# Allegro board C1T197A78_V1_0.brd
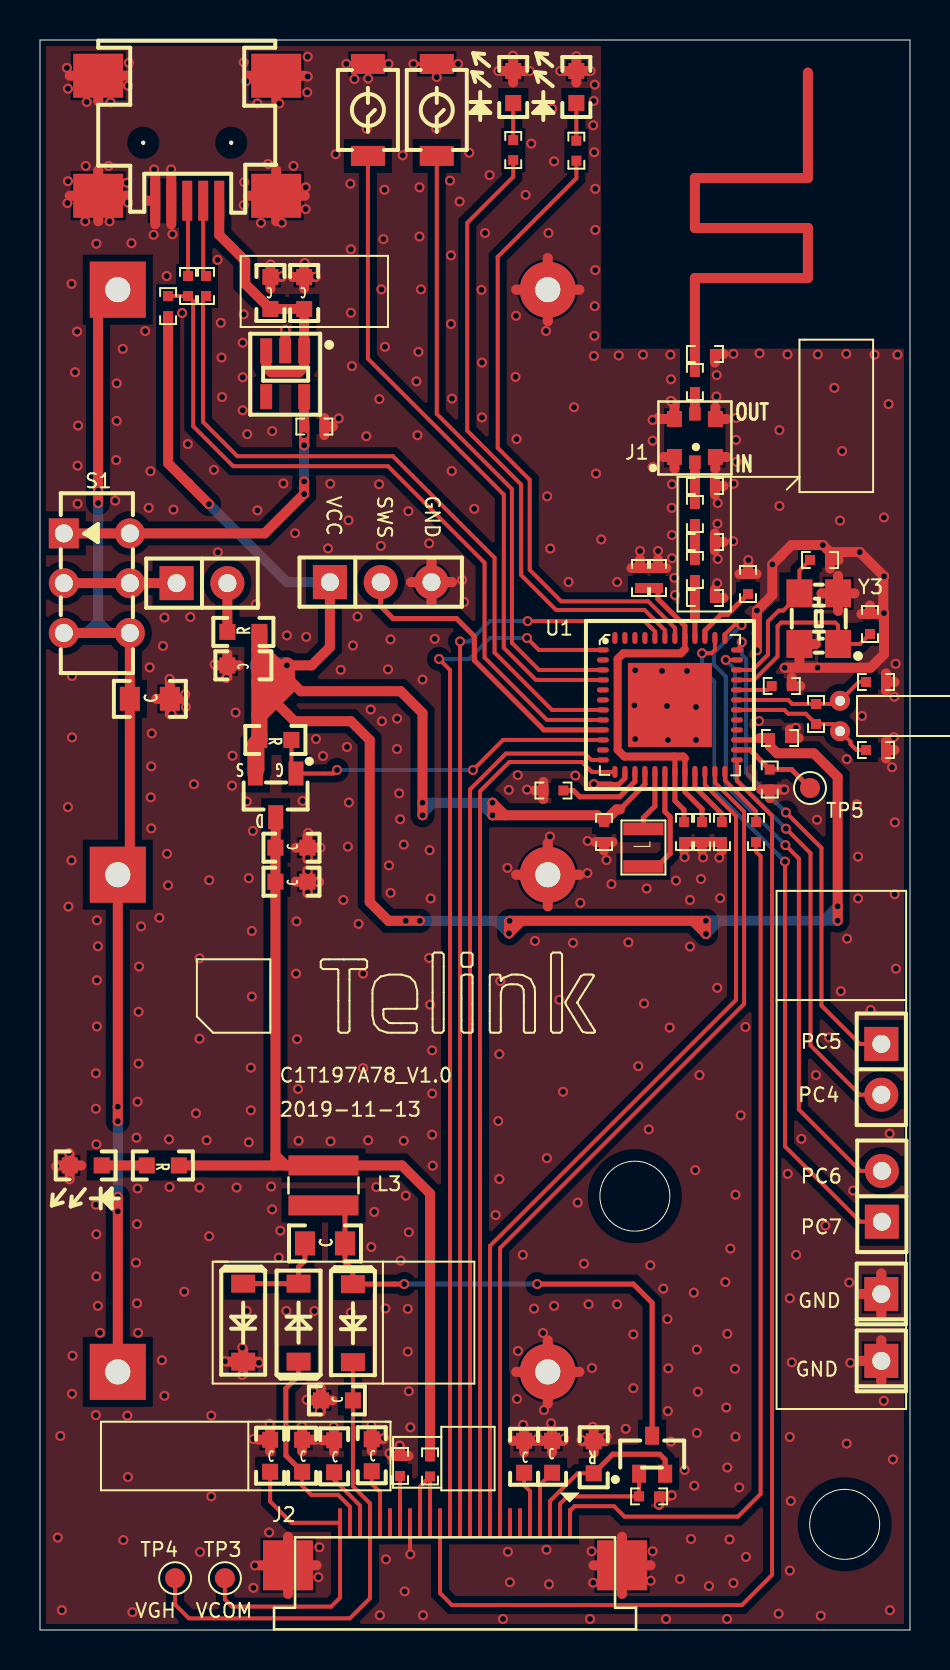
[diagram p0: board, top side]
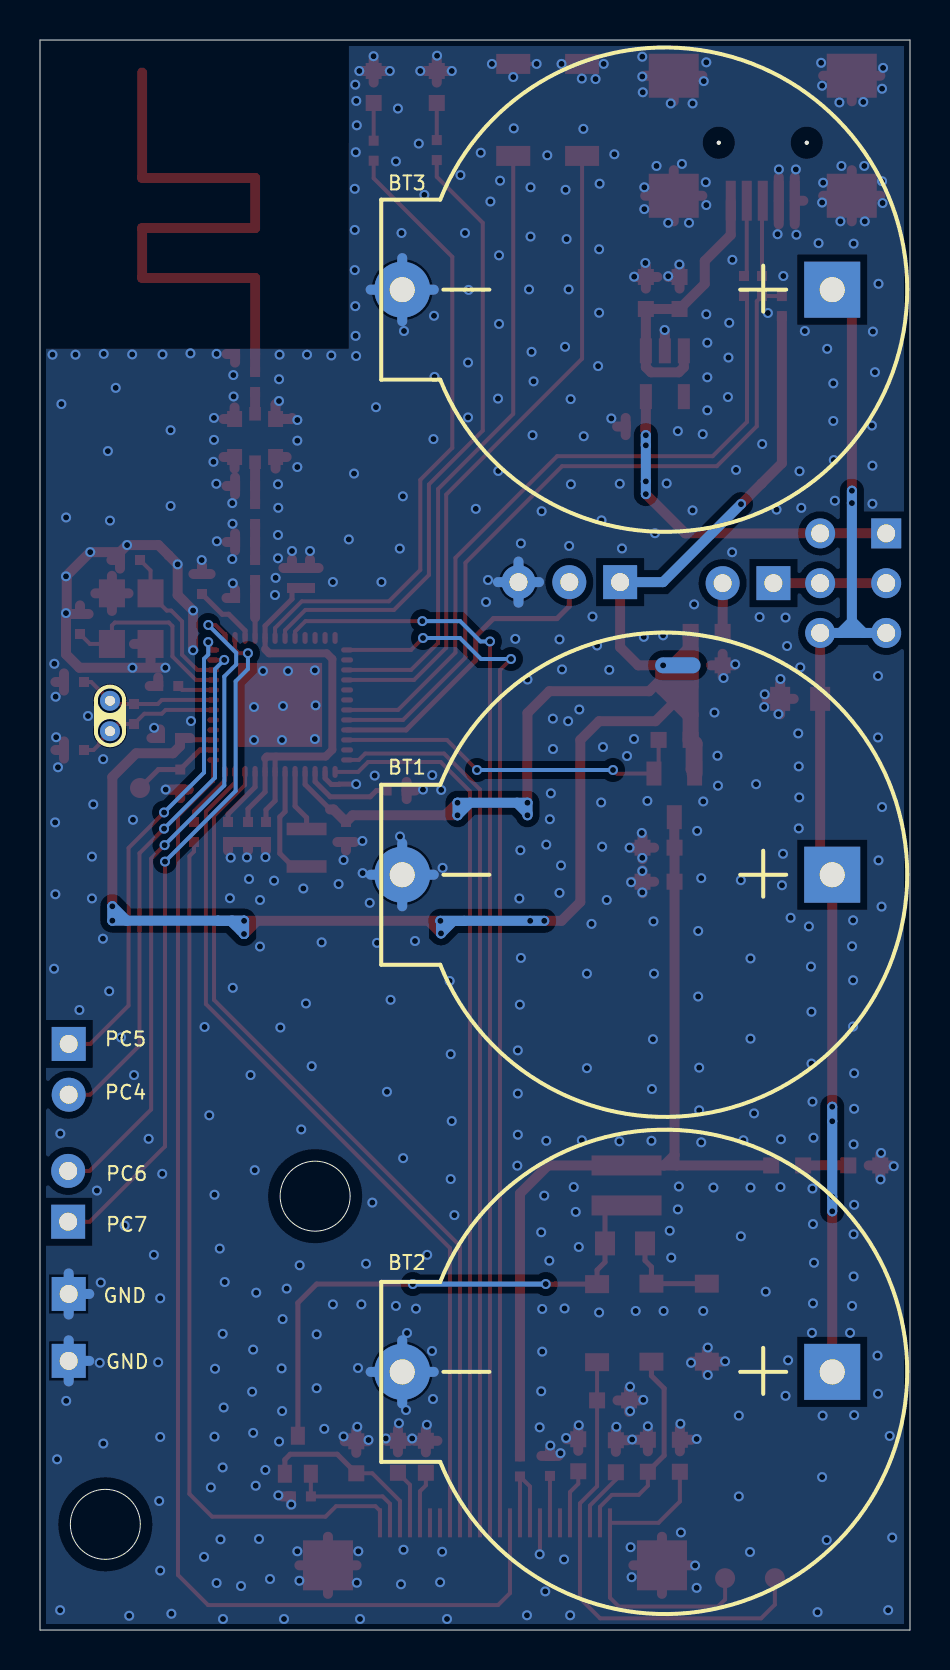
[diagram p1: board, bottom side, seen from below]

Outline 43.5 x 79.5 mm; copper layers: TOP, BOTTOM. Coordinates in mm from the lower left corner of the outline.
Outline path: circle c29.74,21.69 r1.75 ; circle c40.23,5.28 r1.75 ; 0,79.5 0,0 43.5,0 43.5,79.5 0,79.5

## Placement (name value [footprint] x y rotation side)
BT1  3V  [BAT]  13.29 37.76 180 bottom
BT2  3V  [BAT]  13.29 12.91 180 bottom
BT3  3V  [BAT]  13.29 67.02 180 bottom
C1  0.1uF  [0402]  30.9 52.6 270 top
C2  2.2uF  [0402]  30 52.6 270 top
C8  1uF  [0603C]  25.6 8.66 270 top
C9  1uF  [0603C]  24.21 8.66 270 top
C10  NC  [0402]  33.25 54.4 180 top
C11  NC  [0402]  33.25 57.2 180 top
C12  220pF  [0402]  32.75 53 90 top
C13  1uF  [0402]  18 8.2 270 top
C14  NC  [0402]  41.8 47.4 0 top
C15  NC  [0402]  41.8 44 0 top
C16  4.7uF  [0805C]  14.25 19.33 0 top
C17  1uF  [0603C]  14.71 8.69 270 top
C18  1uF  [0603C]  16.59 8.74 270 top
C19  1uF  [0603C]  11.51 8.71 270 top
C20  1uF  [0603C]  14.85 11.48 0 top
C21  1uF  [0603C]  13.11 8.71 270 top
C22  10uF  [0603C]  11.52 66.85 90 top
C23  1uF  [0603C]  12.57 37.41 0 top
C24  10uF  [0603C]  12.57 39.12 0 top
C25  1uF  [0603C]  13.21 66.85 90 top
C26  1uF  [0402]  13.72 60.17 0 top
C27  10uF  [0603C]  10.17 48.23 180 top
C28  10uF  [0805C]  5.49 46.56 0 top
C29  NC  [0402]  33.25 51.6 180 top
C30  NC  [0402]  36.49 42.52 270 top
C31  1uF  [0402]  35.4 52.3 270 top
C32  1uF  [0402]  37 44.6 0 top
C33  1uF  [0402]  25.67 41.97 0 top
C34  1uF  [0402]  37.09 47.2 0 top
C35  1uF  [0402]  28.2 39.9 270 top
C36  NC  [0402]  39 53.5 180 top
C37  NC  [0402]  41.5 50.3 270 top
C38  1uF  [0402]  32.2 39.9 270 top
C39  0.1uF  [0402]  33.1 39.9 270 top
C40  1uF  [0402]  34.1 39.9 270 top
D1  MBR0530  [SOD-123]  10.16 15.37 90 top
D2  MBR0530  [SOD-123]  15.65 15.34 90 top
D3  MBR0530  [SOD-123]  12.93 15.37 270 top
D4  Blue  [0603-LED]  2.29 23.23 180 top
D5  Green  [0603-LED]  26.82 77.15 90 top
D6  Red  [0603-LED]  23.66 77.15 90 top
J1  MM8130  [MM8130-2600]  32.75 59.6 180 top
J2  24FLZ-SM2-GD-TB  [FPC_24PIN]  20.75 5.36 0 top
J5  HEADER 2  [HDR254F-1X2X850]  42.07 26.76 90 top
J6  USB_MiniABF  [USB-MINI-F5]  7.36 71.46 180 top
J7  HEADER 3  [HDR254F-1X3X850]  19.57 52.39 180 top
J8  HEADER1X2  [HDR254F-1X2X850]  9.37 52.34 180 top
J9  HEADER1X1  [HDR254F-1X1X850]  42.06 13.46 90 top
J10  HEADER1X1  [HDR254F-1X1X850]  42.06 16.8 90 top
J15  HEADER 2  [HDR254F-1X2X850]  42.09 22.95 270 top
L3  CD32-10UH  [CD32]  14.17 22.23 0 top
L5  0  [0402]  32.75 55.8 90 top
L6  0  [0402]  32.75 62.4 90 top
L7  4.7uH  [2X2_5MM]  36.92 27.83 90 top
L8  NC  [0402]  33.25 63.8 0 top
Q1  SI1308EDL  [SOT-323]  30.61 8.76 0 top
Q2  PMOS_SI2301  [MOS_SOT-23]  11.79 41.73 180 top
R1  0.47R  [0603R]  27.69 8.64 90 top
R2  1M  [0402]  30.45 6.68 0 top
R4  10R  [0402]  19.5 8.18 270 top
R5  NC  [0402]  38.8 45.8 270 top
R6  1M  [0603R]  11.77 44.5 180 top
R7  3.3K  [0603R]  6.14 23.23 180 top
R8  33  [0402]  8.3 67.2 270 top
R9  33  [0402]  7.4 67.2 270 top
R10  2  [0603R]  10.17 49.91 0 top
R11  750R  [0402]  23.66 74 90 top
R12  750R  [0402]  26.82 73.96 90 top
R13  NC  [0402]  6.41 66.2 270 top
R14  NC/1.5K  [0402]  35.8 39.9 270 top
S1  SW_SL_DPDT  [SW]  2.84 52.34 270 top
SW1  BUT1  [BUTSMD2PX4_00Y3_00_NH]  19.84 76 180 top
SW5  BUT1  [BUTSMD2PX4_00Y3_00_NH]  16.4 76 180 top
TP3  VCOM  [TP100]  9.25 2.59 0 top
TP4  VGH  [TP100]  6.76 2.59 0 top
TP5  VBUS  [TP100]  38.5 42.1 0 top
U1  TLSR8278F1KET48  [QFN_7X7_48PIN_0P5_4P20X4P20]  31.5 46.25 0 top
U2  XC6219_3.3V_SOT-23-5  [SOT-23-5]  12.26 62.81 180 top
Y2  32.768Khz-9pf-+/-20ppm  [OSC_2X6]  44 45.7 180 top
Y3  24MHz-12pF-+/-20ppm  [OSCCC250X320X110]  38.94 50.57 180 top

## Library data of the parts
BT1-BT3 = BATTERY_2xAAA_1
C1 C2 C14 C15 C30 C32 C34 C35 C38-C40 = C1005X5R1C104K
C8 C9 C22-C26 = C1608X5R1C105M
C10-C13 C16-C21 C29 C36 C37 = C1608_NC
C27 C28 = C1608X5R0J106M
C31 C33 = C1005X5R1C105K
D1-D3 = Diode_CDBW0520L-G
D4 = 0603D_Red
D5 D6 = 0603D_Green
J1 = MM8130_1
J2 = CON_2.54mm_1x24
J5 J15 = HEADER 2: Tolerance: RichardLC; User Part Number: pn
J6 = USB_MiniABF_5pin: Tolerance: RichardLC; User Part Number: pn
J7 = HEADER 3: Tolerance: RichardLC; User Part Number: pn
J8 = B2S_3: Tolerance: RichardLC; User Part Number: pn
J9 J10 = CON1: Tolerance: RichardLC; User Part Number: pn
L3 = MLK1608S4N7ST
L5 L6 L8 = MLK1608_000R
L7 = IND_0
Q1 = NMOS_SI2302
Q2 = PMOS_SI2301
R1 R2 R4 = RS0402K000JT
R5 = RS0402_NC
R6 = RS0402K105JT
R7 = RS0402K332JT
R8 R9 = RS0402K330JT
R10 = RS0603K020JT
R11 R12 = RS0402K102JT
R13 R14 = RS0603K152JT
S1 = SW_SL_DPDT_0
SW1 SW5 = SW PUSHBUTTON-SPST/SM
TP3-TP5 = TestPad100
U1 = TLSR8278F1KET48_2
U2 = XC6219_0.3V_SOT-23-5
Y2 = OSC_2x6_2pin
Y3 = CRYSTAL4/SM_0: Tolerance: RichardLC

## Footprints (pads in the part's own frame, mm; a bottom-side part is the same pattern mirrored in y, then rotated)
2X2_5MM
  rect 0.625x2 smd: 1(10.35,6.75) 2(12.225,6.75)
0402
  rect 0.5x0.5 smd: 1(-0.5,0) 2(0.5,0)
0603-LED
  rect 0.8x0.8 smd: A(-0.8,0) C(0.8,0)
0603C
  rect 0.8x0.8 smd: 1(-0.8,0) 2(0.8,0)
0603R
  rect 0.8x0.8 smd: 1(-0.8,0) 2(0.8,0)
0805C
  rect 1x1.2 smd: 1(-1,0) 2(1,0)
BAT
  rect 2.8x2.8 hole 1.254: 1(9.4,0)
  round 2.8 hole 1.254: 2(-12.1,0)
BUTSMD2PX4_00Y3_00_NH
  rect 1.7x1 smd: 1(0,2.3) 2(0,-2.3)
CD32
  rect 3.5x1 smd: 1(0,1) 2(0,-1)
FPC_24PIN
  rect 0.2x1.45 smd: 1(5.75,0) 2(5.25,0) 3(4.75,0) 4(4.25,0) 5(3.75,0) 6(3.25,0) 7(2.75,0) 8(2.25,0) 9(1.75,0) 10(1.25,0) 11(0.75,0) 12(0.25,0) 13(-0.25,0) 14(-0.75,0) 15(-1.25,0) 16(-1.75,0) 17(-2.25,0) 18(-2.75,0) 19(-3.25,0) 20(-3.75,0) 21(-4.25,0) 22(-4.75,0) 23(-5.25,0) 24(-5.75,0)
  rect 2.5x2.5 smd: 25(-8.35,-2.125) 26(8.35,-2.125)
HDR254F-1X1X850
  rect 1.699x1.699 hole 0.899: 1(0,0)
HDR254F-1X2X850
  rect 1.699x1.699 hole 0.899: 1(2.54,0)
  round 1.699 hole 0.899: 2(0,0)
HDR254F-1X3X850
  rect 1.699x1.699 hole 0.899: 1(5.08,0)
  round 1.699 hole 0.899: 2(2.54,0) 3(0,0)
MM8130-2600
  rect 0.58x0.68 smd: 1(0,1.21) 2(0,-1.21)
  rect 0.75x0.8 smd: 3(-1.025,0.95) 4(1.025,0.95) 5(-1.025,-0.95) 6(1.025,-0.95)
MOS_SOT-23
  rect 0.749x1.199 smd: 1(-1.016,-1.092) 2(1.016,-1.092) 3(0,1.092)
OSC_2X6
  round 1 hole 0.5: 1(4,0.76) 2(4,-0.76)
OSCCC250X320X110
  rect 1.3x1.399 smd: 1(-0.965,1.265) 2(-0.965,-1.265) 3(0.965,-1.265) 4(0.965,1.265)
QFN_7X7_48PIN_0P5_4P20X4P20
  oval 0.6x0.26 smd: 1(-3.35,2.75) 2(-3.35,2.25) 3(-3.35,1.75) 4(-3.35,1.25) 5(-3.35,0.75) 6(-3.35,0.25) 7(-3.35,-0.25) 8(-3.35,-0.75) 9(-3.35,-1.25) 10(-3.35,-1.75) 11(-3.35,-2.25) 12(-3.35,-2.75) 25(3.35,-2.75) 26(3.35,-2.25) 27(3.35,-1.75) 28(3.35,-1.25) 29(3.35,-0.75) 30(3.35,-0.25) 31(3.35,0.25) 32(3.35,0.75) 33(3.35,1.25) 34(3.35,1.75) 35(3.35,2.25) 36(3.35,2.75)
  oval 0.26x0.6 smd: 13(-2.75,-3.35) 14(-2.25,-3.35) 15(-1.75,-3.35) 16(-1.25,-3.35) 17(-0.75,-3.35) 18(-0.25,-3.35) 19(0.25,-3.35) 20(0.75,-3.35) 21(1.25,-3.35) 22(1.75,-3.35) 23(2.25,-3.35) 24(2.75,-3.35) 37(2.75,3.35) 38(2.25,3.35) 39(1.75,3.35) 40(1.25,3.35) 41(0.75,3.35) 42(0.25,3.35) 43(-0.25,3.35) 44(-0.75,3.35) 45(-1.25,3.35) 46(-1.75,3.35) 47(-2.25,3.35) 48(-2.75,3.35)
  rect 4.2x4.2 smd: 49(0,0)
SOD-123
  rect 0.899x1.199 smd: A(1.951,0) C(-1.951,0)
SOT-23-5
  rect 0.599x1.25 smd: 1(-0.95,-1.145) 2(0,-1.145) 3(0.95,-1.145) 4(0.95,1.145) 5(-0.95,1.145)
SOT-323
  rect 0.701x0.899 smd: 1(-0.65,-0.95) 2(0.65,-0.95) 3(0,0.95)
SW
  rect 1.5x1.5 hole 0.9: 1(-2.489,-1.651)
  round 1.5 hole 0.9: 2(0,-1.651) 3(2.489,-1.651) 4(2.489,1.651) 5(0,1.651) 6(-2.489,1.651)
TP100
  round 1.001 smd: 1(0,0)
USB-MINI-F5
  round 0.201 hole 0.899 unplated: (-2.2,-2.901) (2.2,-2.901)
  rect 0.5x1.999 smd: 1(-1.6,0) 2(-0.8,0) 3(0,0) 4(0.8,0) 5(1.6,0)
  rect 2.499x2.2 smd: 6(-4.45,-6.251) 7(4.45,-6.251) 8(-4.45,-0.249) 9(4.45,-0.249)

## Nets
1V4: C1.2 C2.2 C38.1 C39.1 U1.19(VDD1V2) U1.20(AVDD1V2#20) U1.41(AVDD1V2#41)
3V3: C26.1 S1.1 S1.6 U2.5(VOUT)
3V3_EPD: C23.1 C24.1 L3.1 Q2.3(D) R4.1 R7.1
GND: BT1.2(-) BT2.2(-) BT3.2(-) C1.1 C2.1 C8.1 C9.1 C10.1 C11.1 C13.1 C14.2 C15.2 C17.1 C18.1 C19.1 C20.1 C21.1 C22.2 C23.2 C24.2 C25.2 C26.2 C27.2 C28.2 C29.1 C30.2 C31.1 C32.2 C33.1 C34.2 C35.2 C36.1 C37.1 C38.2 C39.2 C40.2 D1.C D4.C(CATHODE) D5.C(CATHODE) D6.C(CATHODE) J1.3 J1.4 J1.5 J1.6 J2.17(VSS) J2.25(GND1) J2.26(GND2) J6.4(ID) J6.5(GND) J6.6(S1) J6.7(S2) J6.8(S3) J6.9(S4) J7.3 J9.1 J10.1 L8.2 R1.2 R2.2 SW1.2 SW5.2 U1.14(DVSS) U1.49(GND) U2.2(VSS) Y3.2 Y3.4
TL_3V3: C27.1 C32.1 C35.1 J7.1 Q2.2(S) R6.2 R10.2 R13.2 U1.16(VDD_IO) U1.27(VDD3)
TL_32K01: C14.1 R5.1 U1.31(P1/URX/SCK/32KIN/C[3]) Y2.2
TL_32K02: C15.1 R5.2 U1.30(P0/7816TRX/UTX/SDA/32KO/C[2]) Y2.1
TL_ANT: C12.1 C29.2 U1.40(ANT)
TL_BS1: J2.8(BS1) U1.23(SDMN0/P5/CMP_DF/B[5])
TL_BUSY: J2.9(BUSY) U1.22(SDMP0/P4/CMP_D/B[4])
TL_CK: J2.13(D0) U1.1(CK/SCL/I2SBCK/7816TRX/UTX/D[7])
TL_CS: J2.12(CS) U1.44(CN/I2SLR/P3/D[2])
TL_D/C: J2.11(D/C) U1.12(P5/UCTS/CYC2LNA/B[2])
TL_DM: R8.2 U1.7(DM/A[5])
TL_DO: J2.14(D1) U1.25(SDMN1/DO/URX/B[7])
TL_DP: R9.2 R13.1 U1.8(DP(SWS)/A[6])
TL_GDR: J2.2(GDR) Q1.1(G) R2.1
TL_NC: J2.1(NC) R14.2
TL_PA1: SW1.1 U1.3(DMIC_CLK/7816CLK/I2SCLK/A[1])
TL_PA2: SW5.1 U1.4(DO/UTX/P0/A[2])
TL_PB0: Q2.1(G) R6.1 U1.10(P3/URX/ATSEL1/MDEC/B[0])
TL_PC4: J5.2 U1.35(P2/UCTS/P0/C[4])
TL_PC5: J5.1 U1.36(P3N/URX/ATSEL0/C[5])
TL_PC6: J15.2 U1.37(CYC2LNA/ATSEL1/P4N/C[6])
TL_PC7: J15.1 U1.38(CYC2PA/ATSEL2/P5N/C[7])
TL_PD0: R12.1 U1.42(CYC2LNA/CMP_D/7816TRX/UTX/MDEC/)
TL_PD1: R11.1 U1.43(CYC2PA/CMP_DF/UCTS/D[1])
TL_RES: J2.10(RES) U1.13(P0N/URTS/CYC2PA/B[3])
TL_RESE: J2.3(RESE) Q1.2(S) R1.1
TL_RST: C31.2 U1.39(RESETB)
TL_SWS: J7.2 U1.9(SWS/URTS/A[7])
TL_VBUS: C30.1 TP5.1(TP) U1.26(VBUS)
TL_XC1: C36.2 U1.34(XC1) Y3.3
TL_XC2: C37.2 U1.33(XC2) Y3.1
USB_5V: C22.1 C25.1 J6.1(V_BUS) U2.1(VIN) U2.3(CE)
VCOM: C19.2 J2.24(VCOM) TP3.1(TP)
VGH: C20.2 D2.C J2.21(PREVGH) TP4.1(TP)
N14795340: BT1.1(+) BT2.1(+) BT3.1(+) C28.1 S1.3 S1.4
N14807043: J6.3(D+) R9.1
N14807063: J6.2(D-) R8.1
N14807393: D4.A(ANODE) R7.2
N14811368: J8.1 S1.2 S1.5
N14834347: J8.2 R10.1
N14862027: C13.2 J2.18(VDD)
N14862131: J2.15(VDDIO) J2.16(VCI) R4.2
N14862139: C8.2 J2.4(VGL)
N14862151: C9.2 J2.5(VGH)
N14862215: C21.2 D3.A J2.23(PREVGL)
N14862243: C17.2 J2.22(VSL)
N14862263: C18.2 J2.20(VSH)
N14862345: C16.2 D2.A L3.2 Q1.3(D)
N14862353: C16.1 D1.A D3.C
N14937524: C10.2 C12.2 L5.1
N14937540: C11.2 J1.1 L5.2
N14941034: C34.1 U1.32(VMID)
N14941094: C33.2 U1.15(VDD1V)
N14941130: L7.1 U1.18(VDCDC)
N14941146: L7.2 U1.17(VDCDC_SW)
N14941234: C40.1 U1.21(VDD_F)
N14941494: R14.1 U1.24(SDMP1/DI/SDA/URTS/B[6])
N14949497: L6.2 L8.1
N14951754: J1.2 L6.1
N148761731: D6.A(ANODE) R11.2
N148761931: D5.A(ANODE) R12.2

Pads without a net: J2 6 7 19; U1 2 5 6 11 28 29 45 46 47 48; U2 4

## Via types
v1: diameter 0.5, hole 0.3, TOP to BOTTOM, 581 vias

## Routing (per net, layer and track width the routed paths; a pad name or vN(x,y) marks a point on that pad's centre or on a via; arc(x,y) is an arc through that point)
1V4: length 23.2
  TOP w0.254: C1.2 30.9,51.55 32.25,50.2 U1.41 32.25,49.04 ; 31.7,43.67 31.75,43.63 U1.19 31.75,41.46 32.2,41.01 C38.1 ; 32.25,43.58 U1.20 32.25,41.9 33.1,41.05 C39.1
  TOP w0.4: 32.25,43.58 32.16,43.67 29.22,43.67 28.88,44.01 28.88,48.55 29.17,48.83 32.04,48.83 32.25,49.04
  TOP w0.5: C1.2 C2.2
3V3: length 19.8
  TOP w0.5: 1.19,54.83 11.24,54.83 13.21,56.8 v1(13.21,57.43) ; U2.5 v1(13.21,59.74) v1(13.21,59.23) 13.22,59.24 C26.1
  BOTTOM w0.5: v1(13.21,59.74) v1(13.21,59.23) v1(13.21,57.43) v1(13.21,56.79)
3V3_EPD: length 44.5
  TOP w0.5: 11.66,23.23 12.29,23.23 ; 11.66,23.23 11.77,23.34 11.77,23.75 ; 11.66,23.23 R7.1 ; 12.29,23.23 L3.1 18.1,23.23 19.5,21.82 R4.1 ; 12.29,23.23 11.77,23.75 ; 11.77,23.75 C23.1 C24.1 11.79,39.13 Q2.3
GND: length 201.6
  TOP w0.2: v1(16.41,77.57) 16.4,77.57 SW5.2 ; SW5.2 v1(17.42,78.3) ; SW5.2 15.72,78.3 ; SW1.2 v1(20.9,78.3) ; SW1.2 v1(18.67,78.3) ; SW1.2 v1(19.84,77.65) ; 15.72,78.3 v1(15.32,78.3) ; 15.72,78.3 v1(15.72,77.55) ; v1(18.52,3.78) 18.5,3.78 J2.17
  TOP w0.254: U1.14 29.25,42.59 28.94,42.28 28.56,42.28 28.54,42.29 v1(27.69,42.29)
  TOP w0.5: C18.1 16.59,10.12 ; C18.1 16.59,8.96 ; C18.1 17.16,9.54 ; J6.7 4.34,77.71 ; J6.7 1.48,77.71 ; J6.7 2.91,76.44 ; 34.97,52.8 C31.1 ; C31.1 35.4,53.23 ; C31.1 35.83,52.8 ; 39.9,50.95 Y3.2 ; Y3.2 40.73,51.83 ; Y3.2 39.9,52.71 ; Y3.2 39.07,51.83 ; 11.52,67.07 C22.2 ; C22.2 11.52,68.23 ; C22.2 12.1,67.65 ; 24.74,41.97 C33.1 ; C33.1 25.17,42.4 ; C33.1 25.17,41.55 ; C13.1 18.43,8.7 ; C13.1 17.57,8.7 ; C13.1 18,9.13 ; C37.1 42.16,50.8 42.16,50.81 ; C37.1 41.07,50.8 ; C37.1 41.5,51.23 ; 23.81,37.76 BT1.2 ; BT1.2 25.39,36.19 ; BT1.2 25.39,39.34 ; BT1.2 26.97,37.76 ; C15.2 42.73,44 ; C15.2 42.3,43.57 ; C15.2 42.3,44.43 ; 31.17,58.65 31.72,58.65 31.72,58.07 ; 33.67,39.4 C40.2 34.1,38.97 ; 33.75,52.03 C29.1 34.17,51.6 ; C14.2 42.73,47.4 ; C14.2 42.3,46.97 ; C14.2 42.3,47.83 ; 13.47,11.48 C20.1 ; C20.1 14.62,11.48 ; C20.1 14.05,12.06 ; C20.1 14.05,10.9 ; 27.69,8.86 R1.2 ; R1.2 28.26,9.44 ; R1.2 27.69,10.01 ; R1.2 27.11,9.44 ; v1(37.23,48.11) v1(38.88,48.11) 41.53,48.11 42.2,48.78 v1(42.2,50.85) 42.16,50.81 ; 42.16,50.81 42.16,52.65 v1(42.2,52.68) v1(40.99,53.89) 39.5,53.89 ; 23.63,9.46 C9.1 ; C9.1 24.78,9.46 ; C9.1 24.21,10.04 ; C9.1 24.21,8.88 ; 23.66,77.37 D6.C ; D6.C 23.66,78.53 ; D6.C 23.08,77.95 ; D6.C 24.24,77.95 ; BT3.2 25.39,68.59 ; BT3.2 23.81,67.02 ; BT3.2 26.97,67.02 ; BT3.2 25.39,65.44 ; 34.32,60.55 J1.5 33.77,61.13 ; J6.6 13.24,77.71 ; J6.6 11.81,76.44 ; J6.6 10.38,77.71 ; D5.C 27.4,77.95 ; D5.C 26.82,77.37 ; D5.C 26.24,77.95 ; D5.C 26.82,78.53 ; v1(35.85,48.99) v1(35.85,50.98) 36.62,51.75 v1(36.62,53.28) 37.06,53.73 37.06,53.73 37.58,54.25 v1(39.15,54.25) 39.5,53.89 ; 29.1,1.81 J2.26 ; J2.26 29.1,4.66 ; J2.26 27.67,3.23 ; J2.26 30.53,3.23 ; C26.2 14.64,60.17 ; C26.2 14.22,60.6 ; C26.2 14.22,59.74 ; 33.75,63.37 L8.2 34.17,63.8 ; 0.91,23.23 D4.C ; D4.C 1.49,23.81 ; D4.C 1.49,22.65 ; D4.C 2.06,23.23 ; 2.91,70.43 J6.9 ; J6.9 1.48,71.71 ; J6.9 2.91,72.99 ; J6.9 4.34,71.71 ; 25.03,9.46 C8.1 ; C8.1 25.6,8.88 ; C8.1 25.6,10.04 ; C8.1 26.18,9.46 ; 28.2,38.97 C35.2 ; C35.2 27.77,39.4 ; C35.2 28.63,39.4 ; C27.2 9.37,48.81 ; C27.2 9.95,48.23 ; C27.2 8.79,48.23 ; C27.2 9.37,47.65 ; 41.04,16.8 J10.1 ; J10.1 42.06,15.77 ; J10.1 42.06,17.83 ; 39.5,53.89 C36.1 ; C36.1 39.5,53.07 ; C36.1 39.93,53.5 ; 10.38,71.71 J6.8 ; J6.8 11.81,72.99 ; J6.8 11.81,70.43 ; J6.8 13.24,71.71 ; 41.04,13.46 J9.1 ; J9.1 42.06,12.43 ; J9.1 42.06,14.48 ; C17.1 14.71,10.06 ; C17.1 14.13,9.49 ; C17.1 14.71,8.91 ; 10.93,9.51 C19.1 ; C19.1 11.51,8.93 ; C19.1 11.51,10.09 ; 9.38,13.42 D1.C ; D1.C 10.16,12.79 ; D1.C 10.16,14.04 ; D1.C 10.94,13.42 ; BT2.2 26.97,12.91 ; BT2.2 23.81,12.91 ; BT2.2 25.39,14.48 ; BT2.2 25.39,11.33 ; 6.56,72.64 J6.4 6.56,70.29 ; C2.1 30,53.53 ; C2.1 29.57,53.1 ; C2.1 30.43,53.1 ; C1.1 31.33,53.1 ; C1.1 30.9,53.53 ; C1.1 30.47,53.1 ; 33.1,38.97 C39.2 ; C39.2 33.53,39.4 ; C39.2 32.67,39.4 ; C24.2 13.37,39.69 ; C24.2 12.79,39.12 ; C24.2 13.95,39.12 ; C24.2 13.37,38.54 ; 13.37,36.84 C23.2 ; C23.2 13.95,37.41 ; C23.2 13.37,37.99 ; C23.2 12.79,37.41 ; 37.5,45.03 C32.2 37.93,44.6 ; U2.2 12.26,64.99 v1(12.27,65) ; J7.3 19.57,53.42 ; J7.3 18.55,52.39 ; J7.3 19.57,51.37 ; J7.3 20.6,52.39 ; C10.1 33.75,54.83 ; C10.1 33.75,53.97 ; C10.1 34.17,54.4 ; 33.75,56.77 C11.1 ; C11.1 34.17,57.2 ; C11.1 33.75,57.63 ; 30.95,6.25 R2.2 31.38,6.68 ; 38.02,47.2 C34.2 37.59,47.63 ; 30.9,60.6 30.95,60.55 31.72,60.55 31.72,61.28 v1(31.55,61.45) ; C28.2 7.17,46.56 ; C28.2 6.49,47.34 ; C28.2 5.82,46.56 ; C28.2 6.49,45.78 ; 12.4,1.81 J2.25 ; J2.25 12.4,4.66 ; J2.25 10.97,3.23 ; J2.25 13.83,3.23 ; 37.97,48.42 Y3.4 38.8,49.3 ; C21.1 13.68,9.51 ; C21.1 13.11,10.09 ; C21.1 13.11,8.93 ; 32.2,38.97 C38.2 32.63,39.4 ; 33.77,58.07 J1.3 34.32,58.65 ; C25.2 13.21,68.23 ; C25.2 13.79,67.65 ; C25.2 13.21,67.07 ; C25.2 12.63,67.65 ; C30.2 v1(37.21,42.02) ; C30.2 36.49,41.59 ; C30.2 36.06,42.02 ; 5.76,70.29 J6.5 ; J6.5 5.76,72.64 ; J6.5 5.33,71.46
  BOTTOM w0.5: 19.57,51.37 J7.3 ; J7.3 20.6,52.39 ; J7.3 19.57,53.42 ; J7.3 18.55,52.39 ; 41.04,16.8 J10.1 ; J10.1 42.06,15.77 ; J10.1 42.06,17.83 ; J9.1 42.06,14.48 ; J9.1 42.06,12.43 ; J9.1 41.04,13.46 ; 25.39,65.44 BT3.2 ; BT3.2 25.39,68.59 ; BT3.2 26.97,67.02 ; BT3.2 23.81,67.02 ; 25.39,36.19 BT1.2 ; BT1.2 25.39,39.34 ; BT1.2 23.81,37.76 ; BT1.2 26.97,37.76 ; 25.39,11.33 BT2.2 ; BT2.2 25.39,14.48 ; BT2.2 26.97,12.91 ; BT2.2 23.81,12.91
  vias: v1(0.81,23.19) v1(0.89,4.62) v1(1.02,9.7) v1(1.09,0.99) v1(1.35,78.11) v1(1.4,77.06) v1(1.4,72.44) v1(1.37,71.35) v1(1.4,41.15) v1(1.42,36.17) v1(1.45,23.85) v1(1.47,22.53) v1(1.57,67.31) v1(1.6,47.7) v1(1.6,44.63) v1(1.57,38.48) v1(1.63,13.72) v1(1.6,11.81) v1(1.75,62.89) v1(1.85,64.92) v1(1.91,60.22) v1(1.88,58.22) v1(1.88,56.31) v1(2.34,76.4) v1(2.29,73.2) v1(2.26,70.43) v1(2.82,69.32) v1(2.84,35.48) v1(2.84,32.49) v1(2.84,30.18) v1(2.79,27.84) v1(2.79,26.06) v1(2.82,24.28) v1(2.79,21.26) v1(2.82,19.79) v1(2.82,17.68) v1(2.79,10.74) v1(2.9,34.19) v1(2.9,16.21) v1(3,14.86) v1(3.43,73.2) v1(3.53,76.38) v1(3.48,70.43) v1(3.84,62.33) v1(3.84,60.45) v1(3.81,58.5) v1(3.76,56.46) v1(4.14,64.06) v1(4.17,4.5) v1(4.34,72.36) v1(4.45,78.36) v1(4.39,77.22) v1(4.39,71.37) v1(4.37,10.72) v1(4.39,7.65) v1(4.57,69.34) v1(4.62,0.89) v1(4.83,24.61) v1(4.8,18.36) v1(4.93,30.91) v1(4.93,28.32) v1(4.88,26.42) v1(4.88,22.07) v1(4.85,20.29) v1(4.85,16.33) v1(4.9,14.86) v1(4.95,33.17) v1(5.05,35.18) v1(5.26,64.95) v1(5.44,56.11) v1(5.52,57.94) v1(5.49,48.13) v1(5.54,41.63) v1(5.59,44.83) v1(5.56,43.18) v1(5.56,40.08) v1(5.71,73.03) v1(5.68,69.76) v1(5.97,35.61) v1(6.15,49.2) v1(6.1,13.49) v1(6.22,50.62) v1(6.22,11.71) v1(6.33,67.7) v1(6.35,38.81) v1(6.4,37.24) v1(6.48,47.55) v1(6.45,24.54) v1(6.48,22.15) v1(6.56,73.03) v1(6.62,69.79) v1(6.58,45.8) v1(6.67,56.02) v1(7.11,65.85) v1(7.21,16.92) v1(7.26,46.79) v1(7.29,46.15) v1(7.39,59.3) v1(7.52,50.65) v1(7.7,42.29) v1(7.8,25.83) v1(7.98,33.58) v1(7.98,29.57) v1(7.98,22.12) v1(8,3.9) v1(8.33,24.49) v1(8.46,37.49) v1(8.46,19.68) v1(8.56,10.72) v1(8.56,6.68) v1(8.7,58) v1(8.74,48.29) v1(8.88,68.51) v1(8.89,53.89) v1(9.04,65.36) v1(9.08,63.62) v1(9.1,61.65) v1(9.25,13.44) v1(9.32,47.6) v1(9.63,43.71) v1(9.6,42.21) v1(9.78,45.87) v1(9.83,22.12) v1(10.13,64.36) v1(10.13,62.64) v1(10.13,60.99) v1(10.11,14.12) v1(10.11,12.75) v1(10.19,78.38) v1(10.21,72.39) v1(10.19,71.25) v1(10.19,65.79) v1(10.31,77.44) v1(10.34,41.43) v1(10.34,15.95) v1(10.36,59.79) v1(10.44,37.59) v1(10.44,24.38) v1(10.54,28.12) v1(10.54,25.98) v1(10.64,39.95) v1(10.59,34.95) v1(10.59,31.67) v1(10.67,9.55) v1(10.74,3.23) v1(10.67,2.11) v1(10.79,51.28) v1(10.87,76.33) v1(10.87,55.98) v1(10.95,13.36) v1(11.05,70.36) v1(11.4,73.3) v1(11.53,68.28) v1(11.48,10.31) v1(11.46,4.88) v1(11.61,59.94) v1(11.56,22.17) v1(11.61,21.03) v1(11.94,18.62) v1(11.96,76.33) v1(12.01,19.96) v1(12.09,70.36) v1(12.09,67.69) v1(12.17,57.33) v1(12.34,49.73) v1(12.32,15.95) v1(12.67,73.2) v1(12.75,54.84) v1(12.83,35.43) v1(12.8,32.82) v1(12.85,29.54) v1(12.9,27.05) v1(12.93,24.46) v1(13.13,41.45) v1(13.11,10.19) v1(13.23,68.35) v1(13.28,72.14) v1(13.28,71.04) v1(13.31,49.66) v1(13.34,11.51) v1(13.39,78.66) v1(13.39,77.67) v1(13.36,76.89) v1(13.41,39.85) v1(13.39,38.61) v1(13.39,37.95) v1(13.39,36.88) v1(13.72,15.95) v1(13.79,67.67) v1(13.8,44.55) v1(13.94,37.39) v1(13.89,9.53) v1(13.92,2.64) v1(14.02,39.12) v1(14,12.17) v1(14,10.95) v1(13.97,4.14) v1(14.15,43.7) v1(14.4,54.08) v1(14.51,57.31) v1(14.53,24.43) v1(14.68,10.16) v1(14.78,73.79) v1(14.94,60.58) v1(15.04,48.01) v1(15.16,36.5) v1(15.35,44.15) v1(15.43,55.48) v1(15.44,41.38) v1(15.39,39.17) v1(15.52,72.31) v1(15.54,69.04) v1(15.54,65.86) v1(15.54,15.88) v1(15.6,63.2) v1(15.65,49.23) v1(15.88,50.67) v1(15.93,35.31) v1(16.15,32.82) v1(16.15,28.09) v1(16.33,75.06) v1(16.31,59.69) v1(16.41,24.49) v1(16.54,46.02) v1(16.56,19.15) v1(16.56,10.24) v1(16.71,20.9) v1(16.81,22.15) v1(16.97,61.54) v1(16.96,57.29) v1(17.04,54.2) v1(16.99,0.74) v1(17.07,67.03) v1(17.09,45.44) v1(17.22,72.01) v1(17.17,69.55) v1(17.25,64.16) v1(17.2,9.6) v1(17.27,16.08) v1(17.3,3.53) v1(17.4,48.03) v1(17.45,38.23) v1(17.53,49.53) v1(17.53,36.86) v1(17.48,8.84) v1(17.86,45.57) v1(17.85,44.05) v1(17.96,41.83) v1(18.01,40.54) v1(18.03,18.47) v1(17.98,9.22) v1(18.14,73.74) v1(18.19,39.27) v1(18.19,24.46) v1(18.24,1.93) v1(18.29,21.72) v1(18.42,55.94) v1(18.44,19.89) v1(18.39,16.05) v1(18.39,13.92) v1(18.44,11.94) v1(18.52,10.13) v1(18.82,62.43) v1(18.92,63.91) v1(18.87,59.74) v1(18.97,72.14) v1(18.97,69.67) v1(19.05,67.03) v1(19.13,47.52) v1(19.15,0.74) v1(19.46,54.33) v1(19.48,38.99) v1(19.53,36.58) v1(19.46,33.6) v1(19.51,31.27) v1(19.61,28.98) v1(19.61,26.82) v1(19.61,24.77) v1(19.63,23.22) v1(19.74,49.56) v1(19.81,75.08) v1(20.5,72.47) v1(20.55,68.73) v1(20.55,65.3) v1(20.6,61.57) v1(20.59,57.95) v1(20.98,71.42) v1(21.1,52.5) v1(21.2,51.4) v1(21.46,73.86) v1(21.71,56.06) v1(22.07,67.01) v1(22.1,63.37) v1(22.1,60.63) v1(22.25,69.85) v1(22.48,72.75) v1(22.78,20.74) v1(22.91,77.95) v1(22.91,25.45) v1(23.02,32.45) v1(22.96,28.79) v1(22.96,22.55) v1(23.15,0.55) v1(23.44,42) v1(23.37,38.11) v1(23.39,3.91) v1(23.5,2.39) v1(23.65,78.71) v1(23.8,65.71) v1(23.77,62.66) v1(23.83,59.55) v1(23.89,42.74) v1(23.9,13.95) v1(23.85,11.55) v1(24.14,18.76) v1(24.16,10.26) v1(24.28,71.75) v1(24.35,42.02) v1(24.49,77.95) v1(24.56,74.32) v1(24.7,16.07) v1(24.75,34.45) v1(24.89,9.58) v1(25.15,14.85) v1(25.2,11) v1(25.3,64.95) v1(25.34,23.59) v1(25.32,4.01) v1(25.43,69.85) v1(25.36,56.68) v1(25.51,54.07) v1(25.5,39.67) v1(25.45,2.29) v1(25.6,76.07) v1(25.55,10.34) v1(25.7,73.43) v1(25.7,16.21) v1(26.01,77.95) v1(25.97,31.51) v1(26.15,26.91) v1(26.21,9.58) v1(26.43,52.4) v1(26.65,34.36) v1(26.7,61.14) v1(26.82,78.69) v1(26.77,42.72) v1(26.88,21.37) v1(27.02,36.36) v1(27.08,9.5) v1(27.2,18.31) v1(27.38,39.45) v1(27.37,37.85) v1(27.43,16.28) v1(27.53,77.95) v1(27.5,0.55) v1(27.6,13.1) v1(27.64,10.16) v1(27.58,3.94) v1(27.74,77.27) v1(27.69,76.45) v1(27.66,75.23) v1(27.71,73.89) v1(27.74,66.19) v1(27.72,64.71) v1(27.69,63.7) v1(27.66,2.36) v1(27.76,72.06) v1(27.76,70) v1(27.76,68) v1(27.8,57.82) v1(28.06,54.53) v1(28.32,38.5) v1(28.32,9.68) v1(28.57,37.3) v1(28.94,63.73) v1(28.86,52.4) v1(28.85,16.28) v1(29.29,10.06) v1(29.42,34.38) v1(29.72,46.23) v1(29.67,14.78) v1(29.67,12.09) v1(29.76,47.98) v1(29.76,44.55) v1(29.92,28.19) v1(30,53.95) v1(30.15,63.77) v1(30.2,31.33) v1(30.33,37.08) v1(30.44,25.03) v1(30.52,18.24) v1(30.53,2.46) v1(30.63,60.5) v1(30.63,59.47) v1(30.63,58.15) v1(30.63,3.94) v1(30.9,53.95) v1(30.94,6.27) v1(31.1,47.95) v1(31.17,17.07) v1(31.3,0.55) v1(31.35,46.2) v1(31.4,44.5) v1(31.37,15.54) v1(31.42,13.08) v1(31.39,10.95) v1(31.52,63.77) v1(31.55,62.54) v1(31.48,30.12) v1(31.55,9.42) v1(31.6,57.29) v1(31.59,56.11) v1(31.6,54.75) v1(31.6,53.59) v1(31.58,6.73) v1(31.72,52.61) v1(31.75,51.75) v1(31.8,37.47) v1(32,2.55) v1(32.23,38.64) v1(32.23,8) v1(32.35,47.95) v1(32.5,36.5) v1(32.5,34.17) v1(32.55,4.55) v1(32.69,16.87) v1(32.72,7.21) v1(32.8,46.15) v1(32.8,44.5) v1(32.76,22.99) v1(32.84,14.02) v1(32.84,9.86) v1(32.89,11.91) v1(33.05,37.55) v1(32.97,27.75) v1(33.16,38.63) v1(33.45,2.2) v1(33.83,62.75) v1(33.82,61.68) v1(33.89,56.34) v1(33.87,55.31) v1(33.89,53.55) v1(33.86,52.33) v1(33.86,32.11) v1(33.97,38.62) v1(34,36.59) v1(34.26,17.4) v1(34.32,11.13) v1(34.37,14.81) v1(34.37,8.13) v1(34.35,0.55) v1(34.51,19.07) v1(34.48,4.53) v1(34.67,63.81) v1(34.68,57.31) v1(34.66,54.44) v1(34.75,13.06) v1(34.67,2.35) v1(34.8,60.6) v1(34.8,59.51) v1(34.83,58.41) v1(34.78,21.76) v1(34.78,9.67) v1(35.04,25.73) v1(34.96,7.13) v1(35.27,30.15) v1(35.3,3.66) v1(35.42,53.5) v1(35.98,63.83) v1(35.95,45.45) v1(36.93,0.81) v1(36.97,59.99) v1(36.97,56.2) v1(37.38,63.78) v1(37.39,22.81) v1(37.49,16.59) v1(37.49,9.65) v1(37.54,6.45) v1(37.49,2.97) v1(37.59,13.39) v1(37.79,45.11) v1(37.81,18.76) v1(38.07,24.56) v1(38.8,27.75) v1(38.89,63.78) v1(38.85,40.51) v1(39.04,0.71) v1(39.27,20.22) v1(39.45,29.63) v1(39.71,62.11) v1(40,55.47) v1(40.04,31.94) v1(40.11,58.95) v1(40.31,63.81) v1(40.34,43.54) v1(40.34,9.32) v1(40.35,34.57) v1(40.46,17.37) v1(40.51,13.36) v1(40.65,21.97) v1(40.84,41.28) v1(40.9,38.67) v1(40.9,36.58) v1(41.1,45.7) v1(41.53,31) v1(41.73,63.77) v1(42.2,55.63) v1(42.19,11.46) v1(42.43,61.3) v1(42.48,24.82) v1(42.49,0.99) v1(42.6,43.14) v1(42.65,8.53) v1(42.72,46.66) v1(42.69,44.64) v1(42.74,40.38) v1(42.73,36.79) v1(42.78,48.31) v1(42.8,33.06) v1(42.88,63.77)
TL_3V3: length 136.7
  TOP w0.254: 36,44.6 35.91,44.5 U1.27 ; 29,41.03 30.25,42.28 U1.16
  TOP w0.5: 24.08,35.46 v1(23.45,34.83) 23.45,35.43 v1(23.48,35.46) 24.08,35.46 ; 24.08,35.46 32.64,35.46 ; J7.1 14.49,49.14 13.59,48.23 v1(12.34,48.23) 11.75,48.23 ; 23.25,40.74 27.86,40.74 C35.1 28.83,41.03 29,41.03 ; 23.25,40.74 v1(22.62,40.74) v1(22.62,41.36) 23.25,40.74 ; 32.64,35.46 v1(33.3,35.46) 33.3,34.8 ; 32.64,35.46 33.3,34.8 ; v1(18.99,35.46) v1(18.29,35.46) 17.42,35.46 16.48,36.4 16.48,44.5 15.54,45.44 12.73,45.44 10.97,47.2 ; v1(19.13,40.74) v1(19.13,41.36) 19.13,45.85 18.03,46.94 13.04,46.94 11.75,48.23 ; 11.75,48.23 C27.1 ; R6.2 10.97,43.02 Q2.2 ; 33.3,34.8 v1(33.3,34.8) ; R13.2 6.41,58.34 7.42,57.32 v1(8.45,56.29) ; 36,44.6 C32.1 36.5,44.19 36.85,43.84 38.69,43.84 39.88,42.65 v1(39.88,36.19) v1(39.88,35.47)
  TOP w0.8: 10.97,49.01 R10.2 ; 10.97,49.01 11.75,48.23 11.7,48.18 ; 10.97,49.01 C27.1 10.97,47.45 ; 10.97,47.45 11.7,48.18 ; 10.97,47.45 10.97,45.77 ; 11.7,48.18 11.7,46.47 ; v1(12.34,48.23) 12.34,47.12 11.7,46.47 ; 10.97,45.77 11,45.77 11.7,46.47 ; 10.97,45.77 R6.2 10.77,44.3 Q2.2
  BOTTOM w0.5: 39.17,35.47 v1(39.88,36.19) v1(39.88,35.47) 39.17,35.47 ; 39.17,35.47 34.6,35.47 ; 22.83,35.45 23.15,35.45 23.45,35.15 ; 22.83,35.45 v1(23.45,34.83) 23.45,35.15 ; 22.83,35.45 22.3,35.45 22.29,35.46 ; v1(33.3,35.46) 34.59,35.46 34.6,35.47 ; v1(33.3,35.46) 33.3,34.8 v1(33.3,34.8) ; v1(33.3,35.46) 33.3,35.46 ; 22,41.36 v1(22.62,40.74) v1(22.62,41.36) 22,41.36 ; 22,41.36 19.65,41.36 ; 33.3,35.46 33.3,35.47 33.9,35.47 ; 33.3,35.46 v1(33.3,34.8) ; 22.29,35.46 v1(23.48,35.46) 23.45,35.43 23.45,35.15 ; 22.29,35.46 v1(18.99,35.46) v1(18.29,35.46) ; 34.6,35.47 33.9,35.47 ; 33.9,35.47 33.9,35.4 v1(33.3,34.8) ; 19.65,41.36 v1(19.13,41.36) 19.13,40.83 ; 19.65,41.36 19.65,41.35 19.13,40.83 ; J7.1 12.35,52.39 v1(8.45,56.29) ; 19.13,40.83 v1(19.13,40.74)
  BOTTOM w0.8: v1(12.34,48.23) 10.87,48.23
TL_32K01: length 7
  TOP w0.2: U1.31 37.41,46.5 37.61,46.3 R5.1 39.84,46.3 Y2.2 40.94,47.4 C14.1
TL_32K02: length 7.4
  TOP w0.2: U1.30 37.22,46 37.41,45.81 38.28,45.81 R5.2 39.64,45.3 Y2.1 40.53,44.41 40.53,44.29 40.82,44 C15.1
TL_ANT: length 2.9
  TOP w0.254: 32.75,50.62 U1.40
  TOP w0.5: C12.1 C29.2 32.75,50.62
TL_BS1: length 43.2
  TOP w0.2: J2.8 23,19.1 35.2,31.3 35.2,40.92 33.75,42.38 U1.23
TL_BUSY: length 43.3
  TOP w0.2: U1.22 33.25,42.25 34.8,40.7 34.8,31.5 22.5,19.21 J2.9
TL_CK: length 52.3
  TOP w0.2: v1(19.95,48.55) 20.5,48 J2.13 ; v1(24.35,49.6) 24.95,49 U1.1
  BOTTOM w0.2: v1(24.35,49.6) 22.5,49.6 21.45,48.55 v1(19.95,48.55)
TL_CS: length 54.8
  TOP w0.2: U1.44 30.75,49.92 30.22,50.44 v1(24.38,50.44) ; J2.12 v1(21,49.43)
  BOTTOM w0.2: v1(21,49.43) 21.48,49.43 22.49,50.44 v1(24.38,50.44)
TL_D/C: length 44.2
  TOP w0.2: J2.11 21.5,42.03 23.3,43.82 27.24,43.82 27.56,43.5 U1.12
TL_DM: length 35.1
  TOP w0.2: R8.2 8.15,66.55 8.15,60.4 9.87,58.69 12.97,58.69 12.98,58.68 13.44,58.68 13.44,58.69 17.65,58.69 22.73,53.61 22.73,48.87 25.6,46 U1.7
TL_DO: length 62.5
  TOP w0.2: J2.14 20,1.84 20.6,1.25 35.1,1.25 36.6,2.75 36.6,40.7 34.85,42.46 U1.25
TL_DP: length 37
  TOP w0.2: U1.8 25.35,45.5 22.23,48.62 22.23,53.36 17.4,58.19 9.66,58.19 7.66,60.19 7.66,66.44 R9.2 R13.1
TL_GDR: length 6.2
  TOP w0.2: J2.2 26,6.31 26.37,6.68 R2.1 29.96,6.68 Q1.1
TL_NC: length 43.6
  TOP w0.2: J2.1 26.5,5.96 26.73,6.19 28.7,6.19 29.22,5.67 34.89,5.67 36.03,6.8 36.03,38.69 35.8,38.92 R14.2
TL_PA1: length 31
  TOP w0.2: SW1.1 19.84,60.81 23.6,57.05 23.6,49.35 24.95,48 U1.3
TL_PA2: length 33
  TOP w0.2: U1.4 24.8,47.5 23.19,49.11 23.19,56.77 16.4,63.56 SW5.1
TL_PB0: length 17.8
  TOP w0.2: R6.1 12.57,43.06 Q2.1 14.67,42.82 v1(14.85,43) ; v1(21.65,43) 23.15,44.5 U1.10
  BOTTOM w0.2: v1(14.85,43) v1(21.65,43)
TL_PC4: length 26.1
  TOP w0.2: J5.2 40.99,26.76 38.53,29.23 38.53,38.84 v1(37.3,40.07) ; U1.35 v1(34.29,48.5)
  BOTTOM w0.2: v1(37.3,40.07) 34.75,42.61 34.75,48.04 v1(34.29,48.5)
TL_PC5: length 24.1
  TOP w0.2: U1.36 35.09,49.25 v1(35.09,49.39) ; J5.1 40.99,29.3 39.07,31.22 39.07,39.1 v1(37.3,40.88)
  BOTTOM w0.2: v1(35.09,49.39) 35.09,48.77 35.3,48.56 35.3,42.88 v1(37.3,40.88)
TL_PC6: length 33.2
  TOP w0.2: U1.37 34.25,49.77 34.72,50.25 v1(35.08,50.25) ; v1(37.27,39.24) 37.94,38.57 37.94,26.03 41.01,22.95 J15.2
  BOTTOM w0.2: v1(37.27,39.24) 34.29,42.23 34.29,47.68 33.69,48.27 33.69,48.86 v1(35.08,50.25)
TL_PC7: length 34.1
  TOP w0.2: v1(33.1,48.84) 33.58,48.84 33.75,49.01 U1.38 ; v1(37.25,38.42) 37.25,24.18 41.02,20.41 J15.1
  BOTTOM w0.2: v1(33.1,48.84) 33.1,48.05 33.72,47.43 33.72,41.95 v1(37.25,38.42)
TL_PD0: length 31.7
  TOP w0.2: U1.42 31.75,50.1 30.41,51.44 26.05,51.44 24.49,53 24.49,57.51 22.89,59.11 22.89,68.66 26.82,72.59 R12.1
TL_PD1: length 31.5
  TOP w0.2: R11.1 23.66,72.66 21.36,70.36 21.36,59.97 24.05,57.28 24.05,52.75 25.8,51 30.23,51 31.25,49.99 U1.43
TL_RES: length 44.1
  TOP w0.2: J2.10 22,41.94 23.46,43.4 27.1,43.4 27.59,42.9 U1.13
TL_RESE: length 8.6
  TOP w0.2: R1.1 26.89,7.84 25.5,6.45 J2.3
  TOP w0.254: R1.1 28.64,8.79 30.99,8.79 31.26,8.52 Q1.2
TL_RST: length 3.3
  TOP w0.254: U1.39 33.25,49.97 34.06,50.79 34.39,50.79 C31.2
TL_SWS: length 15.6
  TOP w0.254: J7.2 17.04,51.19 17.65,50.57 20.83,50.57 21.72,49.68 21.72,48.48 25.2,45 U1.9
TL_VBUS: length 4.4
  TOP w0.254: U1.26 35.51,44 C30.1 37.58,43.02 TP5.1
TL_XC1: length 7.6
  TOP w0.2: C36.2 37.97,52.97 Y3.3 37.97,51.78 37.16,50.97 36.94,50.97 36.4,50.43 36.4,48.76 35.64,48 U1.34
TL_XC2: length 9.9
  TOP w0.2: U1.33 35.7,47.5 36.88,48.68 36.88,50.19 37.06,50.37 39.76,50.37 39.9,50.23 Y3.1 41,49.3 C37.2
USB_5V: length 14
  TOP w0.5: J6.1 8.96,69.75 10.26,68.45 10.26,67.31 C22.1 C25.1 U2.1 13.21,63.14 12.95,62.88 11.56,62.88 11.31,63.14 U2.3
VCOM: length 16.3
  TOP w0.2: C19.2 11.51,6.43 12.57,5.36 J2.24 15,1.62 14.55,1.17 9.6,1.17 9.25,1.52 TP3.1
VGH: length 23.9
  TOP w0.2: D2.C C20.2 15.65,7.19 16.5,6.33 J2.21 16.5,1.59 15.49,0.58 7.44,0.58 6.76,1.27 TP4.1
N14795340: length 64.5
  TOP w0.5: v1(2.91,56.35) v1(2.91,56.96) 2.91,66.03 BT3.1 ; BT2.1 v1(3.89,20.94) v1(3.89,21.66) ; S1.3 2.17,49.85 2.17,49.85 3.57,49.85 3.57,49.85 S1.4 C28.1 4.49,38.37 BT1.1 v1(3.89,26.16) v1(3.89,25.44)
  BOTTOM w0.5: 2.91,50.44 2.32,49.85 ; 2.91,50.44 2.91,50.42 3.48,49.85 ; 2.91,50.44 v1(2.91,56.35) v1(2.91,56.96) ; 2.32,49.85 3.48,49.85 ; 2.32,49.85 S1.3 ; 3.48,49.85 S1.4 ; v1(3.89,20.94) v1(3.89,21.66) v1(3.89,25.44) v1(3.89,26.16)
N14807043: length 3.8
  TOP w0.2: J6.3 7.4,71.42 R9.1
N14807063: length 3.8
  TOP w0.2: R8.1 8.16,67.84 J6.2
N14807393: length 2.3
  TOP w0.5: R7.2 D4.A
N14811368: length 5.6
  TOP w0.5: S1.2 S1.5 J8.1
N14834347: length 2.4
  TOP w0.5: J8.2 R10.1
N14862027: length 2.3
  TOP w0.2: J2.18 C13.2
N14862131: length 4.8
  TOP w0.2: J2.15 R4.2 19,7.18 J2.16
N14862139: length 2.8
  TOP w0.2: J2.4 25,7.26 C8.2
N14862151: length 2.6
  TOP w0.2: C9.2 24.21,7.23 24.5,6.94 J2.5
N14862215: length 10.4
  TOP w0.2: J2.23 15.5,6.16 14.9,6.76 13.56,6.76 13.11,7.21 C21.2
  TOP w0.254: C21.2 12.29,8.72 12.29,12.08 12.93,12.71 D3.A
N14862243: length 3.1
  TOP w0.2: J2.22 16,6.22 14.71,7.52 C17.2
N14862263: length 2.8
  TOP w0.2: C18.2 16.59,7.31 17,6.89 J2.20
N14862345: length 26.9
  TOP w0.254: Q1.3 30.61,16.36 29.67,17.3 v1(24.86,17.3) ; v1(18.21,17.3) 17.71,17.3 17.7,17.29 D2.A 15.65,18 15.25,18.39 C16.2 15.25,20.84 14.87,21.23 L3.2
  BOTTOM w0.254: v1(24.86,17.3) v1(18.21,17.3)
N14862353: length 4.9
  TOP w0.254: C16.1 13.25,18.48 12.93,18.15 D3.C D1.A
N14937524: length 1.8
  TOP w0.5: C12.2 C10.2 L5.1
N14937540: length 2.1
  TOP w0.5: L5.2 C11.2 J1.1
N14941034: length 1.8
  TOP w0.2: C34.1 36.39,47 U1.32
N14941094: length 4.5
  TOP w0.254: C33.2 26.67,41.97 26.99,41.66 28.99,41.66 29.75,42.42 U1.15
N14941130: length 5.8
  TOP w0.254: U1.18 31.25,40.92 31.51,40.65 31.51,38.83 30.86,38.18 L7.1
N14941146: length 3.1
  TOP w0.254: L7.2 30.17,40.62 30.75,41.19 U1.17
N14941234: length 3.1
  TOP w0.254: C40.1 34.1,40.79 32.75,42.15 U1.21
N14941494: length 3.1
  TOP w0.2: U1.24 34.25,42.49 35.8,40.94 R14.1
N14949497: length 31.9
  TOP w0.5: L6.2 L8.1 32.75,67.6 38.4,67.6 38.4,70.1 32.75,70.1 32.75,72.6 38.4,72.6 38.4,77.87
N14951754: length 1.1
  TOP w0.5: J1.2 L6.1
N148761731: length 1.9
  TOP w0.2: D6.A R11.2
N148761931: length 1.9
  TOP w0.2: D5.A R12.2

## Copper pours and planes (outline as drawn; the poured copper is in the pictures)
GND on TOP: 0.3,0.3 0.3,79.2 28.06,79.2 28.06,71.72 28.06,71.72 28.06,64.07 32,64.07 32,61.1 31.21,61.1 31.21,58.12 32,58.12 32,48.75 33.5,48.75 33.5,58.12 34.27,58.12 34.27,61.1 33.5,61.1 33.5,64.07 43.2,64.07 43.2,0.3 ; 9 cut-outs
GND on BOTTOM: 0.3,0.3 0.3,79.2 28.06,79.2 28.06,74.34 28.06,74.34 28.06,64.07 43.2,64.07 43.2,0.3 ; 2 cut-outs

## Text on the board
Ref Des/Silkscreen Bottom: PC6 | PC7 | GND | PC5 | PC4
Ref Des/Silkscreen Top: VGH | VCOM | C1T197A78_V1.0 | 2019-11-13 | GND | PC4 | PC5 | PC6 | PC7 | VCC | SWS
COMPVAL_TYPE_TOP: 2019-11-13 | C1T197A78_V1.0
BODY_CENTER: FIGURE | SIZE | 0.3 | 0.5 | 0.8992 | 0.9 | 1.254 | DRILL CHART: TOP to BOTTOM | ALL UNITS ARE IN MILLIMETERS | PLATED | NON-PLATED | QTY | 581 | 2 | 11 | 6
